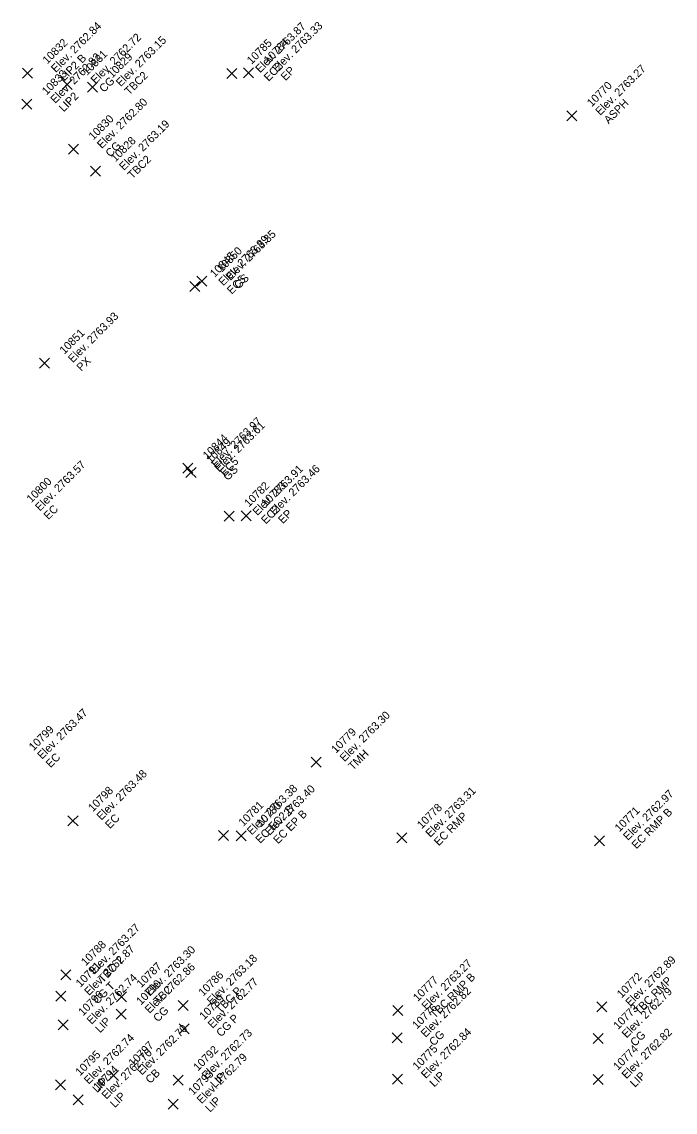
# Model space of a CAD drawing. Extents: x 2493999 to 2503109, y 700767 to 706646.
# Drawn here: x 2502458.03 to 2502477.61, y 701358.69 to 701391.38 of the extents above; entities that cross this region are included whole.
import ezdxf

# ---------------------------------------------------------------- set-up
doc = ezdxf.new("R2010")
doc.units = 0
doc.layers.add('ALG_CL_BLUE_Horiz', color=7, linetype='Continuous')
doc.layers.add('DES_SURFACE_Existing-Ground', color=7, linetype='Continuous')

msp = doc.modelspace()

# ---------------------------------------------------------------- linework, layer by layer
at = {"layer": 'ALG_CL_BLUE_Horiz'}
for points in [[(2502464.828, 701389.851), (2502464.678, 701390.001), (2502464.828, 701389.851), (2502464.678, 701389.701), (2502464.828, 701389.851), (2502464.978, 701389.701), (2502464.828, 701389.851), (2502464.978, 701390.001)], [(2502458.204, 701389.842), (2502458.054, 701389.992), (2502458.204, 701389.842), (2502458.054, 701389.692), (2502458.204, 701389.842), (2502458.354, 701389.692), (2502458.204, 701389.842), (2502458.354, 701389.992)], [(2502464.323, 701389.833), (2502464.173, 701389.983), (2502464.323, 701389.833), (2502464.173, 701389.683), (2502464.323, 701389.833), (2502464.473, 701389.683), (2502464.323, 701389.833), (2502464.473, 701389.983)], [(2502459.393, 701389.501), (2502459.243, 701389.651), (2502459.393, 701389.501), (2502459.243, 701389.351), (2502459.393, 701389.501), (2502459.543, 701389.351), (2502459.393, 701389.501), (2502459.543, 701389.651)], [(2502460.148, 701389.419), (2502459.998, 701389.569), (2502460.148, 701389.419), (2502459.998, 701389.269), (2502460.148, 701389.419), (2502460.298, 701389.269), (2502460.148, 701389.419), (2502460.298, 701389.569)], [(2502458.184, 701388.914), (2502458.034, 701389.064), (2502458.184, 701388.914), (2502458.034, 701388.764), (2502458.184, 701388.914), (2502458.334, 701388.764), (2502458.184, 701388.914), (2502458.334, 701389.064)], [(2502474.511, 701388.559), (2502474.361, 701388.709), (2502474.511, 701388.559), (2502474.361, 701388.409), (2502474.511, 701388.559), (2502474.661, 701388.409), (2502474.511, 701388.559), (2502474.661, 701388.709)], [(2502459.582, 701387.562), (2502459.432, 701387.712), (2502459.582, 701387.562), (2502459.432, 701387.412), (2502459.582, 701387.562), (2502459.732, 701387.412), (2502459.582, 701387.562), (2502459.732, 701387.712)], [(2502460.245, 701386.906), (2502460.095, 701387.056), (2502460.245, 701386.906), (2502460.095, 701386.756), (2502460.245, 701386.906), (2502460.395, 701386.756), (2502460.245, 701386.906), (2502460.395, 701387.056)], [(2502463.219, 701383.447), (2502463.069, 701383.597), (2502463.219, 701383.447), (2502463.069, 701383.297), (2502463.219, 701383.447), (2502463.369, 701383.297), (2502463.219, 701383.447), (2502463.369, 701383.597)], [(2502463.43, 701383.604), (2502463.28, 701383.754), (2502463.43, 701383.604), (2502463.28, 701383.454), (2502463.43, 701383.604), (2502463.58, 701383.454), (2502463.43, 701383.604), (2502463.58, 701383.754)], [(2502458.712, 701381.143), (2502458.562, 701381.293), (2502458.712, 701381.143), (2502458.562, 701380.993), (2502458.712, 701381.143), (2502458.862, 701380.993), (2502458.712, 701381.143), (2502458.862, 701381.293)], [(2502463.004, 701377.993), (2502462.854, 701378.143), (2502463.004, 701377.993), (2502462.854, 701377.843), (2502463.004, 701377.993), (2502463.154, 701377.843), (2502463.004, 701377.993), (2502463.154, 701378.143)], [(2502463.102, 701377.864), (2502462.952, 701378.014), (2502463.102, 701377.864), (2502462.952, 701377.714), (2502463.102, 701377.864), (2502463.252, 701377.714), (2502463.102, 701377.864), (2502463.252, 701378.014)], [(2502464.244, 701376.56), (2502464.094, 701376.71), (2502464.244, 701376.56), (2502464.094, 701376.41), (2502464.244, 701376.56), (2502464.394, 701376.41), (2502464.244, 701376.56), (2502464.394, 701376.71)], [(2502464.75, 701376.567), (2502464.6, 701376.717), (2502464.75, 701376.567), (2502464.6, 701376.417), (2502464.75, 701376.567), (2502464.9, 701376.417), (2502464.75, 701376.567), (2502464.9, 701376.717)], [(2502466.85, 701369.181), (2502466.7, 701369.331), (2502466.85, 701369.181), (2502466.7, 701369.031), (2502466.85, 701369.181), (2502467, 701369.031), (2502466.85, 701369.181), (2502467, 701369.331)], [(2502459.567, 701367.426), (2502459.417, 701367.576), (2502459.567, 701367.426), (2502459.417, 701367.276), (2502459.567, 701367.426), (2502459.717, 701367.276), (2502459.567, 701367.426), (2502459.717, 701367.576)], [(2502464.073, 701366.985), (2502463.923, 701367.135), (2502464.073, 701366.985), (2502463.923, 701366.835), (2502464.073, 701366.985), (2502464.223, 701366.835), (2502464.073, 701366.985), (2502464.223, 701367.135)], [(2502464.603, 701366.971), (2502464.453, 701367.121), (2502464.603, 701366.971), (2502464.453, 701366.821), (2502464.603, 701366.971), (2502464.753, 701366.821), (2502464.603, 701366.971), (2502464.753, 701367.121)], [(2502469.42, 701366.915), (2502469.27, 701367.065), (2502469.42, 701366.915), (2502469.27, 701366.765), (2502469.42, 701366.915), (2502469.57, 701366.765), (2502469.42, 701366.915), (2502469.57, 701367.065)], [(2502475.343, 701366.822), (2502475.193, 701366.972), (2502475.343, 701366.822), (2502475.193, 701366.672), (2502475.343, 701366.822), (2502475.493, 701366.672), (2502475.343, 701366.822), (2502475.493, 701366.972)], [(2502459.354, 701362.808), (2502459.204, 701362.958), (2502459.354, 701362.808), (2502459.204, 701362.658), (2502459.354, 701362.808), (2502459.504, 701362.658), (2502459.354, 701362.808), (2502459.504, 701362.958)], [(2502459.198, 701362.168), (2502459.048, 701362.318), (2502459.198, 701362.168), (2502459.048, 701362.018), (2502459.198, 701362.168), (2502459.348, 701362.018), (2502459.198, 701362.168), (2502459.348, 701362.318)], [(2502461.018, 701362.151), (2502460.868, 701362.301), (2502461.018, 701362.151), (2502460.868, 701362.001), (2502461.018, 701362.151), (2502461.168, 701362.001), (2502461.018, 701362.151), (2502461.168, 701362.301)], [(2502462.871, 701361.892), (2502462.721, 701362.042), (2502462.871, 701361.892), (2502462.721, 701361.742), (2502462.871, 701361.892), (2502463.021, 701361.742), (2502462.871, 701361.892), (2502463.021, 701362.042)], [(2502469.301, 701361.741), (2502469.151, 701361.891), (2502469.301, 701361.741), (2502469.151, 701361.591), (2502469.301, 701361.741), (2502469.451, 701361.591), (2502469.301, 701361.741), (2502469.451, 701361.891)], [(2502475.408, 701361.845), (2502475.258, 701361.995), (2502475.408, 701361.845), (2502475.258, 701361.695), (2502475.408, 701361.845), (2502475.558, 701361.695), (2502475.408, 701361.845), (2502475.558, 701361.995)], [(2502461.01, 701361.632), (2502460.86, 701361.782), (2502461.01, 701361.632), (2502460.86, 701361.482), (2502461.01, 701361.632), (2502461.16, 701361.482), (2502461.01, 701361.632), (2502461.16, 701361.782)], [(2502459.273, 701361.308), (2502459.123, 701361.458), (2502459.273, 701361.308), (2502459.123, 701361.158), (2502459.273, 701361.308), (2502459.423, 701361.158), (2502459.273, 701361.308), (2502459.423, 701361.458)], [(2502462.899, 701361.187), (2502462.749, 701361.337), (2502462.899, 701361.187), (2502462.749, 701361.037), (2502462.899, 701361.187), (2502463.049, 701361.037), (2502462.899, 701361.187), (2502463.049, 701361.337)], [(2502469.276, 701360.915), (2502469.126, 701361.065), (2502469.276, 701360.915), (2502469.126, 701360.765), (2502469.276, 701360.915), (2502469.426, 701360.765), (2502469.276, 701360.915), (2502469.426, 701361.065)], [(2502475.301, 701360.899), (2502475.151, 701361.049), (2502475.301, 701360.899), (2502475.151, 701360.749), (2502475.301, 701360.899), (2502475.451, 701360.749), (2502475.301, 701360.899), (2502475.451, 701361.049)], [(2502460.778, 701359.787), (2502460.628, 701359.937), (2502460.778, 701359.787), (2502460.628, 701359.637), (2502460.778, 701359.787), (2502460.928, 701359.637), (2502460.778, 701359.787), (2502460.928, 701359.937)], [(2502459.188, 701359.509), (2502459.038, 701359.659), (2502459.188, 701359.509), (2502459.038, 701359.359), (2502459.188, 701359.509), (2502459.338, 701359.359), (2502459.188, 701359.509), (2502459.338, 701359.659)], [(2502462.718, 701359.654), (2502462.568, 701359.804), (2502462.718, 701359.654), (2502462.568, 701359.504), (2502462.718, 701359.654), (2502462.868, 701359.504), (2502462.718, 701359.654), (2502462.868, 701359.804)], [(2502469.288, 701359.682), (2502469.138, 701359.832), (2502469.288, 701359.682), (2502469.138, 701359.532), (2502469.288, 701359.682), (2502469.438, 701359.532), (2502469.288, 701359.682), (2502469.438, 701359.832)], [(2502475.297, 701359.675), (2502475.147, 701359.825), (2502475.297, 701359.675), (2502475.147, 701359.525), (2502475.297, 701359.675), (2502475.447, 701359.525), (2502475.297, 701359.675), (2502475.447, 701359.825)], [(2502459.72, 701359.062), (2502459.57, 701359.212), (2502459.72, 701359.062), (2502459.57, 701358.912), (2502459.72, 701359.062), (2502459.87, 701358.912), (2502459.72, 701359.062), (2502459.87, 701359.212)], [(2502462.571, 701358.926), (2502462.421, 701359.076), (2502462.571, 701358.926), (2502462.421, 701358.776), (2502462.571, 701358.926), (2502462.721, 701358.776), (2502462.571, 701358.926), (2502462.721, 701359.076)]]:
    msp.add_lwpolyline(points, dxfattribs=at)

# ---------------------------------------------------------------- texts
at = {"layer": 'DES_SURFACE_Existing-Ground'}
for s, p in [('Elev. 2762.84', (2502459.053, 701389.842)), ('Elev. 2763.87', (2502465.172, 701389.833)), ('Elev. 2763.33', (2502465.677, 701389.851)), ('Elev. 2762.72', (2502460.242, 701389.501)), ('10832', (2502458.798, 701390.097)), ('Elev. 2763.15', (2502460.997, 701389.419)), ('10785', (2502464.917, 701390.088)), ('10784', (2502465.422, 701390.106)), ('Elev. 2762.82', (2502459.033, 701388.914)), ('LIP2 B', (2502459.307, 701389.587)), ('10831', (2502459.987, 701389.756)), ('10829', (2502460.742, 701389.674)), ('EC2', (2502465.426, 701389.578)), ('EP', (2502465.931, 701389.596)), ('Elev. 2763.27', (2502475.36, 701388.559)), ('10833', (2502458.778, 701389.169)), ('CG', (2502460.496, 701389.246)), ('TBC2', (2502461.251, 701389.164)), ('10770', (2502475.105, 701388.814)), ('LIP2', (2502459.287, 701388.659)), ('Elev. 2762.80', (2502460.431, 701387.562)), ('ASPH', (2502475.614, 701388.304)), ('10830', (2502460.176, 701387.817)), ('Elev. 2763.19', (2502461.094, 701386.906)), ('CG', (2502460.685, 701387.307)), ('10828', (2502460.839, 701387.161)), ('TBC2', (2502461.348, 701386.651)), ('Elev. 2763.35', (2502464.279, 701383.604)), ('Elev. 2763.89', (2502464.068, 701383.447)), ('10845', (2502463.813, 701383.702)), ('10850', (2502464.024, 701383.859)), ('GS', (2502464.533, 701383.349)), ('EC5', (2502464.322, 701383.192)), ('Elev. 2763.93', (2502459.561, 701381.143)), ('10851', (2502459.306, 701381.398)), ('PX', (2502459.815, 701380.888)), ('Elev. 2763.97', (2502463.853, 701377.993)), ('Elev. 2763.61', (2502463.951, 701377.864)), ('10844', (2502463.598, 701378.248)), ('10849', (2502463.696, 701378.119)), ('Elev. 2763.57', (2502458.575, 701376.691)), ('EC5', (2502464.107, 701377.738)), ('GS', (2502464.205, 701377.609)), ('Elev. 2763.91', (2502465.093, 701376.56)), ('Elev. 2763.46', (2502465.599, 701376.567)), ('10800', (2502458.32, 701376.946)), ('10782', (2502464.838, 701376.815)), ('10783', (2502465.344, 701376.822)), ('EC', (2502458.829, 701376.436)), ('EC2', (2502465.347, 701376.305)), ('EP', (2502465.853, 701376.312)), ('Elev. 2763.47', (2502458.64, 701369.253)), ('Elev. 2763.30', (2502467.699, 701369.181)), ('10799', (2502458.385, 701369.508)), ('10779', (2502467.444, 701369.436)), ('EC', (2502458.894, 701368.998)), ('TMH', (2502467.953, 701368.926)), ('Elev. 2763.48', (2502460.416, 701367.426)), ('10798', (2502460.161, 701367.681)), ('Elev. 2763.38', (2502464.922, 701366.985)), ('Elev. 2763.40', (2502465.452, 701366.971)), ('Elev. 2763.31', (2502470.269, 701366.915)), ('Elev. 2762.97', (2502476.192, 701366.822)), ('10781', (2502464.667, 701367.24)), ('EC EC2 B', (2502465.176, 701366.73)), ('10780', (2502465.197, 701367.226)), ('10778', (2502470.014, 701367.17)), ('10771', (2502475.937, 701367.077)), ('EC RMP B', (2502476.446, 701366.567)), ('EC', (2502460.67, 701367.171)), ('EC EP B', (2502465.706, 701366.716)), ('EC RMP', (2502470.523, 701366.66)), ('Elev. 2763.27', (2502460.203, 701362.808)), ('10788', (2502459.948, 701363.063)), ('Elev. 2762.87', (2502460.047, 701362.168)), ('Elev. 2763.30', (2502461.867, 701362.151)), ('TBC T', (2502460.457, 701362.553)), ('10787', (2502461.612, 701362.406)), ('Elev. 2763.18', (2502463.72, 701361.892)), ('Elev. 2763.27', (2502470.15, 701361.741)), ('Elev. 2762.89', (2502476.257, 701361.845)), ('10791', (2502459.792, 701362.423)), ('Elev. 2762.86', (2502461.859, 701361.632)), ('10786', (2502463.465, 701362.147)), ('TBC RMP B', (2502470.404, 701361.486)), ('Elev. 2762.74', (2502460.122, 701361.308)), ('CG T', (2502460.301, 701361.913)), ('10790', (2502461.604, 701361.887)), ('Elev. 2762.77', (2502463.748, 701361.187)), ('10777', (2502469.895, 701361.996)), ('10772', (2502476.002, 701362.1)), ('TBC RMP', (2502476.511, 701361.59)), ('10796', (2502459.867, 701361.563)), ('TBC', (2502462.121, 701361.896)), ('TBC P', (2502463.974, 701361.637)), ('Elev. 2762.82', (2502470.125, 701360.915)), ('Elev. 2762.79', (2502476.15, 701360.899)), ('10789', (2502463.493, 701361.442)), ('10776', (2502469.87, 701361.17)), ('10773', (2502475.895, 701361.154)), ('CG', (2502462.113, 701361.377)), ('CG P', (2502464.002, 701360.932)), ('LIP', (2502460.376, 701361.053)), ('Elev. 2762.70', (2502461.627, 701359.787)), ('Elev. 2762.74', (2502460.037, 701359.509)), ('Elev. 2762.73', (2502463.567, 701359.654)), ('Elev. 2762.84', (2502470.137, 701359.682)), ('CG', (2502470.379, 701360.66)), ('Elev. 2762.82', (2502476.146, 701359.675)), ('CG', (2502476.404, 701360.644)), ('Elev. 2762.70', (2502460.569, 701359.062)), ('10797', (2502461.372, 701360.042)), ('10792', (2502463.312, 701359.909)), ('10775', (2502469.882, 701359.937)), ('10774', (2502475.891, 701359.93)), ('10795', (2502459.782, 701359.764)), ('Elev. 2762.79', (2502463.42, 701358.926)), ('10794', (2502460.314, 701359.317)), ('CB', (2502461.881, 701359.532)), ('10793', (2502463.165, 701359.181)), ('LIP', (2502460.291, 701359.254)), ('LIP', (2502463.821, 701359.399)), ('LIP', (2502470.391, 701359.427)), ('LIP', (2502476.4, 701359.42)), ('LIP', (2502460.823, 701358.807)), ('LIP', (2502463.674, 701358.671))]:
    msp.add_text(s, height=0.24, rotation=45, dxfattribs=at).set_placement(p)

doc.saveas('drawing.dxf')
